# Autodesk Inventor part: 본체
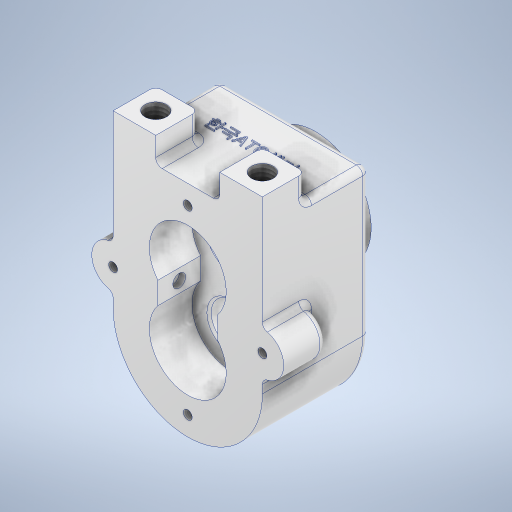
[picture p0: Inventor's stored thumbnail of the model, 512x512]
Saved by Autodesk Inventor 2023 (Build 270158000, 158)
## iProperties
Created: 2024-03
Part Number: 본체
Material: 알루미늄 6061
Document SubType Name: Modeling
Designer: asung
Density: 2.7 g/cm^3
Appearance: 알루미늄 - 평지
Author: asung
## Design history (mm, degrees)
sketch "스케치1"
  geometry: L1 (0, 0)-(0, 68); L2 (-35, 0)-(-35, 68); L3 (35, 0)-(35, 68); L4 (-35, 68)-(35, 68); C1 r 35 at (0, 0); 3 further points
  constraints: 8 end point, 2 parallel, 1 centre point, 1 coincident, 1 horizontal, 1 vertical
  dimensions: "d0" = 70 diameter of C1; "d1" = 68 distance of L1.start L1.end; "d2" = 35 distance between parallel lines of L1 L2; "d3" = 35 distance between parallel lines of L1 L3; "d4" = 68 distance from line of point (0, 0) L4; "d5" = 68 distance from line of L3.start L4; "d6" = 68 distance from line of L2.start L4
extrude "돌출1" new body sketch "스케치1" stored distance "d7" = 50; taper "d8" = 0 deg
sketch "스케치2"
  geometry: L1 (0, 50)-(0, 0) reference; L2 (70, 0)-(0, 0) reference; L3 (70, 0)-(70, 50) reference; L4 (0, 50)-(70, 50) reference; L5 (0, 0)-(20, 0); L6 (20, 0)-(20, 20); L7 (20, 20)-(0, 20); L8 (0, 20)-(0, 0); L9 (70, 0)-(50, 0); L10 (50, 0)-(50, 20); L11 (50, 20)-(70, 20); L12 (70, 20)-(70, 0); 5 further points
  constraints: 16 end point, 4 parallel, 2 horizontal, 2 perpendicular
  dimensions: "d9" = 20 distance of L7.end L6.end; "d10" = 20 distance of L6.end L5.end; "d11" = 20 distance of L10.end L11.end; "d12" = 20 distance of L9.end L10.end
extrude "돌출2" join sketch "스케치2" distance "d13" = 12; taper "d14" = 0 deg
fillet "모깎기1" dims "d15" = 3
fillet "모깎기2" dims "d16" = 3
sketch "스케치3"
  geometry: L1 (12, 68)-(-12, 68) reference; L2 (-15, 71)-(-15, 80) reference; L3 (-35, 80)-(-15, 80) reference; L4 (-35, 0)-(-35, 80) reference; L5 (35, 0)-(35, 80) reference; L6 (15, 80)-(35, 80) reference; L7 (15, 71)-(15, 80) reference; L8 (0, 68)-(0, 40); C1 r 10 at (-35, 16.5); C2 r 10 at (35, 16.5); A1 r 3 centre (-12, 71) between (-15, 71) and (-12, 68) reference; A2 r 35 centre (0, 0) between (-35, 0) and (35, 0) reference; A3 r 3 centre (12, 71) between (12, 68) and (15, 71) reference; 5 further points
  constraints: 2 centre point, 2 end point, 1 midpoint, 1 point on line, 1 symmetric about line, 1 vertical, 1 other
  dimensions: "d17" = 10 radius of C1; "d18" = 63.5 distance from line of C1.centre L3
extrude "돌출3" join sketch "스케치3" distance "d19" = 20; taper "d20" = 0 deg
fillet "모깎기3" dims "d21" = 3
fillet "모깎기4" dims "d22" = 3
sketch "스케치4"
  geometry: L1 (12, 68)-(-12, 68) reference; L2 (-15, 71)-(-15, 80) reference; L3 (-35, 80)-(-15, 80) reference; L4 (-35, 29.149)-(-35, 80) reference; L5 (-35, 0)-(-35, 3.851) reference; L6 (35, 0)-(35, 3.851) reference; L7 (35, 29.149)-(35, 80) reference; L8 (15, 80)-(35, 80) reference; L9 (15, 71)-(15, 80) reference; L10 (0, 33)-(0, 0); L11 (-14, 21.686)-(-14, 11.314); L12 (14, 21.686)-(14, 11.314); A1 r 3 centre (-12, 71) between (-15, 71) and (-12, 68) reference; A2 r 3 centre (-38, 29.149) between (-37.308, 26.23) and (-35, 29.149) reference; A3 r 10 centre (-35, 16.5) between (-37.308, 26.23) and (-37.308, 6.77) reference; A4 r 3 centre (-38, 3.851) between (-35, 3.851) and (-37.308, 6.77) reference; A5 r 35 centre (0, 0) between (-35, 0) and (35, 0) reference; A6 r 3 centre (38, 3.851) between (37.308, 6.77) and (35, 3.851) reference; A7 r 10 centre (35, 16.5) between (37.308, 6.77) and (37.308, 26.23) reference; A8 r 3 centre (38, 29.149) between (35, 29.149) and (37.308, 26.23) reference; A9 r 3 centre (12, 71) between (12, 68) and (15, 71) reference; A10 r 18 centre (0, 33) between (14, 21.686) and (-14, 21.686); A11 r 18 centre (0, 0) between (-14, 11.314) and (14, 11.314); 2 further points
  constraints: 6 end point, 4 point on circle, 2 centre point, 2 parallel, 1 midpoint, 1 vertical, 1 vertical alignment
  dimensions: "d23" = 36 diameter of A10; "d24" = 35 distance from line of L10.start L1; "d25" = 36 diameter of A11; "d26" = 33 distance of L10.end L10.start; "d27" = 14 distance between parallel lines of L10 L11; "d28" = 14 distance between parallel lines of L10 L12
extrude "돌출4" cut sketch "스케치4" distance "d29" = 20; taper "d30" = 0 deg
sketch "스케치5"
  geometry: L1 (35, 68)-(-35, 68) reference; L2 (-35, 68)-(-35, 0) reference; L3 (35, 0)-(35, 68) reference; C1 r 26 at (0, 33); A1 r 35 centre (0, 0) between (-35, 0) and (35, 0) reference; 2 further points
  constraints: 1 centre point, 1 midpoint, 1 vertical alignment
  dimensions: "d31" = 52 diameter of C1; "d32" = 35 distance from line of L1 C1.centre
extrude "돌출5" join sketch "스케치5" distance "d33" = 10; taper "d34" = 0 deg
sketch "스케치6"
  geometry: C1 r 26 at (0, 0) reference; C2 r 16 at (0, 0); A1 r 18 centre (0, 0) between (14, -11.314) and (-14, -11.314) reference; 1 further point
  constraints: 1 centre point, 1 coincident
  dimensions: "d35" = 32 diameter of C2
extrude "돌출6" join sketch "스케치6" distance "d36" = 4; taper "d37" = 0 deg
chamfer "모따기1" distance "d38" = 1; stored, may be unused: second distance "d39" = 2, angle "d40" = 45 deg
fillet "모깎기5" dims "d41" = 3
sketch "스케치7"
  geometry: A1 r 18 centre (0, 33) between (14, 21.686) and (-14, 21.686) reference; 2 further points
  constraints: 1 coincident
hole "구멍1" sketch "스케치7" at (0, 33) diameter "d42" = 15; stored, may be unused: countersink angle "d46" = 90 deg, drill point angle "d48" = 0 deg; dims "d43" = 8, "d44" = 20, "d45" = 10, "d47" = 30
sketch "스케치8"
  geometry: C1 r 15 at (0, 0) reference; 2 further points
  constraints: 1 coincident
hole "구멍2" sketch "스케치8" at (0, 0) diameter "d49" = 15; stored, may be unused: countersink angle "d53" = 90 deg, drill point angle "d55" = 0 deg; dims "d50" = 6, "d51" = 25, "d52" = 7.3, "d54" = 30
sketch "스케치9"
  geometry: A1 r 18 centre (0, 0) between (-14, 11.314) and (14, 11.314) reference; 2 further points
  constraints: 1 coincident
hole "구멍3" sketch "스케치9" at (0, 0) diameter "d59" = 20; stored, may be unused: countersink angle "d63" = 90 deg, drill point angle "d65" = 0 deg; dims "d60" = 6, "d61" = 25, "d62" = 7.3, "d64" = 10
chamfer "모따기3" distance "d66" = 1; stored, may be unused: second distance "d67" = 2, angle "d68" = 45 deg
sketch "스케치10"
  geometry: L1 (7, -35)-(7, -28) reference; L2 (17, -35)-(7, -35) reference; L3 (17, -38)-(17, -35) reference; L4 (18, -39)-(17, -38) reference; L5 (25.5, -31.7)-(20.5, -31.7) reference; L6 (25.5, -5)-(25.5, -31.7) reference; L7 (23, -5)-(25.5, -5) reference; L8 (43, 5)-(51, 5) reference; L9 (51, 5)-(51, 25) reference; L10 (51, 25)-(68, 25) reference; L11 (68, 25)-(68, -25) reference; L12 (68, -25)-(62, -25) reference; L13 (4, -25)-(-35, -25) reference; L14 (-35, -25)-(-35, 25) reference; L15 (-35, 25)-(-18, 25) reference; L16 (-18, 25)-(-18, 5) reference; L17 (-18, 5)-(-11, 5) reference; L18 (-11, 5)-(-10, 4) reference; L19 (-10, 4)-(-10, -5) reference; L20 (-10, -5)-(10, -5) reference; L21 (10, -5)-(10, 4) reference; L22 (10, 4)-(11, 5) reference; L23 (11, 5)-(23, 5) reference; L24 (40.5, -5)-(43, -5) reference; L25 (40.5, -31.7)-(40.5, -5) reference; L26 (45.5, -31.7)-(40.5, -31.7) reference; L27 (49, -38)-(48, -39) reference; L28 (49, -35)-(49, -38) reference; L29 (59, -35)-(49, -35) reference; L30 (59, -28)-(59, -35) reference; L31 (0, -25)-(0, 25) reference; L32 (10, -5)-(-10, -5) reference; L33 (7, -5)-(0, -9.041); L34 (23, 5)-(23, -5) reference; L35 (20.5, -31.7)-(20.5, -39) reference; L36 (20.5, -39)-(18, -39) reference; L37 (48, -39)-(45.5, -39) reference; L38 (45.5, -39)-(45.5, -31.7) reference; L39 (43, -5)-(43, 5) reference; A1 r 3 centre (4, -28) between (4, -25) and (7, -28) reference; A2 r 3 centre (62, -28) between (59, -28) and (62, -25) reference; 3 further points
  constraints: 2 end point, 2 point on line
  dimensions: "d70" = 7 distance from line of L31 L33.start; "d71" = 60 deg angle of L31 L33
revolve "회전1" sketch "스케치10" stored, may be unused: angle "d72" = 90 deg
sketch "스케치11"
  geometry: L1 (0, 0)-(0, -26); L2 (-14, 11.314)-(-14, 21.686) reference; L3 (14, 21.686)-(14, 11.314) reference; L4 (12, 68)-(-12, 68) reference; L5 (-15, 71)-(-15, 80) reference; L6 (-35, 80)-(-15, 80) reference; L7 (-35, 29.149)-(-35, 80) reference; L8 (-35, 0)-(-35, 3.851) reference; L9 (35, 0)-(35, 3.851) reference; L10 (35, 29.149)-(35, 80) reference; L11 (15, 80)-(35, 80) reference; L12 (15, 71)-(15, 80) reference; L13 (0, 33)-(0, 59); C1 r 29 at (0, 33) reference; A1 r 18 centre (0, 0) between (-14, 11.314) and (14, 11.314) reference; A2 r 18 centre (0, 33) between (14, 21.686) and (-14, 21.686) reference; A3 r 3 centre (-12, 71) between (-15, 71) and (-12, 68) reference; A4 r 3 centre (-38, 29.149) between (-37.308, 26.23) and (-35, 29.149) reference; A5 r 10 centre (-35, 16.5) between (-37.308, 26.23) and (-37.308, 6.77) reference; A6 r 3 centre (-38, 3.851) between (-35, 3.851) and (-37.308, 6.77) reference; A7 r 35 centre (0, 0) between (-35, 0) and (35, 0) reference; A8 r 3 centre (38, 3.851) between (37.308, 6.77) and (35, 3.851) reference; A9 r 10 centre (35, 16.5) between (37.308, 6.77) and (37.308, 26.23) reference; A10 r 3 centre (38, 29.149) between (35, 29.149) and (37.308, 26.23) reference; A11 r 3 centre (12, 71) between (12, 68) and (15, 71) reference; 4 further points
  constraints: 4 coincident, 4 end point, 2 vertical
  dimensions: "d73" = 26 distance of L1.start L1.end; "d74" = 26 distance of L13.start L13.end
hole "구멍4" sketch "스케치11" at (0, -26), (35, 16.5), (-35, 16.5), (0, 59) diameter "d75" = 4.134; stored, may be unused: countersink angle "d79" = 90 deg, drill point angle "d81" = 118 deg; dims "d76" = 10, "d77" = 4, "d78" = 2, "d80" = 12
sketch "스케치12" dims "d82" = 42
  geometry: C1 r 26 at (0, 0) reference; C2 r 7.5 at (0, 0) reference; 3 further points
  constraints: 1 coincident, 1 vertical alignment, 2 other
hole "구멍5" sketch "스케치12" at (0, 21) diameter "d83" = 3.242; stored, may be unused: countersink angle "d87" = 90 deg, drill point angle "d89" = 118 deg; dims "d84" = 8, "d85" = 4, "d86" = 2, "d88" = 10
sketch "스케치13"
  geometry: L1 (18, -39)-(17, -38) reference; L2 (17, -38)-(17, -35) reference; L3 (17, -35)-(13.621, -35) reference; L4 (13.621, -35)-(13.621, -25) reference; L5 (13.621, -25)-(12, -24.026) reference; L6 (12, -24.026)-(10.379, -25) reference; L7 (10.379, -25)-(10.379, -35) reference; L8 (10.379, -35)-(7, -35) reference; L9 (7, -35)-(7, -28) reference; L10 (4, -25)-(-35, -25) reference; L11 (-35, -25)-(-35, 25) reference; L12 (-35, 25)-(-28.067, 25) reference; L13 (-28.067, 25)-(-28.067, 13) reference; L14 (-28.067, 13)-(-26, 11.758) reference; L15 (-26, 11.758)-(-23.933, 13) reference; L16 (-23.933, 13)-(-23.933, 25) reference; L17 (-23.933, 25)-(-18, 25) reference; L18 (-18, 25)-(-18, 5) reference; L19 (-18, 5)-(-11, 5) reference; L20 (-11, 5)-(-10, 4) reference; L21 (-10, 4)-(-10, -5) reference; L22 (-10, -5)-(-7, -5) reference; L23 (-7, -5)-(0, -9.041) reference; L24 (0, -9.041)-(7, -5) reference; L25 (7, -5)-(10, -5) reference; L26 (10, -5)-(10, 4) reference; L27 (10, 4)-(11, 5) reference; L28 (11, 5)-(23, 5) reference; L29 (23, 5)-(23, -5) reference; L30 (23, -5)-(25.5, -5) reference; L31 (25.5, -5)-(25.5, -31.7) reference; L32 (25.5, -31.7)-(20.5, -31.7) reference; L33 (20.5, -31.7)-(20.5, -39) reference; L34 (20.5, -39)-(18, -39) reference; L35 (49, -38)-(48, -39) reference; L36 (48, -39)-(45.5, -39) reference; L37 (45.5, -39)-(45.5, -31.7) reference; L38 (45.5, -31.7)-(40.5, -31.7) reference; L39 (40.5, -31.7)-(40.5, -5) reference; L40 (40.5, -5)-(43, -5) reference; L41 (43, -5)-(43, 5) reference; L42 (43, 5)-(51, 5) reference; L43 (51, 5)-(51, 25) reference; L44 (51, 25)-(56.933, 25) reference; L45 (56.933, 25)-(56.933, 13) reference; L46 (56.933, 13)-(59, 11.758) reference; L47 (59, 11.758)-(61.067, 13) reference; L48 (61.067, 13)-(61.067, 25) reference; L49 (61.067, 25)-(68, 25) reference; L50 (68, 25)-(68, -25) reference; L51 (68, -25)-(62, -25) reference; L52 (59, -28)-(59, -35) reference; L53 (59, -35)-(55.621, -35) reference; L54 (55.621, -35)-(55.621, -25) reference; L55 (55.621, -25)-(54, -24.026) reference; L56 (54, -24.026)-(52.379, -25) reference; L57 (52.379, -25)-(52.379, -35) reference; L58 (52.379, -35)-(49, -35) reference; L59 (49, -35)-(49, -38) reference; L60 (45.5, -31.7)-(45.5, -39) reference; L61 (45.5, -38.3)-(45.904, -39); L62 (48, -39)-(18, -39) reference; L63 (33, -39)-(33, -30); A1 r 3 centre (4, -28) between (7, -28) and (4, -25) reference; A2 r 3 centre (62, -28) between (62, -25) and (59, -28) reference; 4 further points
  constraints: 4 end point, 2 midpoint, 2 point on line, 1 vertical
  dimensions: "d93" = 0.7 vertical distance of L61.start point (46.75, -39); "d94" = 30 deg angle of L37 L61
revolve "회전2" sketch "스케치13" stored, may be unused: angle "d95" = 90 deg
sketch "스케치15"
  geometry: L1 (17, 20)-(0, 20) reference; L2 (0, 20)-(0, 0) reference; L3 (0, 0)-(20, 0) reference; L4 (20, 0)-(20, 17) reference; L5 (50, 17)-(50, 0) reference; L6 (50, 0)-(70, 0) reference; L7 (70, 0)-(70, 20) reference; L8 (70, 20)-(53, 20) reference; A1 r 3 centre (17, 17) between (20, 17) and (17, 20) reference; A2 r 3 centre (53, 17) between (53, 20) and (50, 17) reference; 3 further points
  dimensions: "d103" = 10 distance from line of L1 point (10, 10); "d104" = 10 distance from line of L4 point (10, 10); "d105" = 10 distance from line of L8 point (60, 10); "d106" = 10 distance from line of L7 point (60, 10)
hole "구멍6" sketch "스케치15" at (10, 10), (60, 10) diameter "d107" = 10.106; stored, may be unused: countersink angle "d111" = 90 deg, drill point angle "d113" = 0 deg; dims "d108" = 14, "d109" = 4, "d110" = 2, "d112" = 16
node "작업 평면1"
sketch "스케치16"
  geometry: L1 (14, 11.314)-(14, 21.686) reference; L2 (-14, 21.686)-(-14, 11.314) reference; L3 (-12, 68)-(12, 68) reference; L4 (15, 71)-(15, 80) reference; L5 (15, 80)-(19.947, 80) reference; L6 (19.947, 80)-(19.947, 64) reference; L7 (19.947, 64)-(30.053, 64) reference; L8 (30.053, 64)-(30.053, 80) reference; L9 (30.053, 80)-(35, 80) reference; L10 (35, 80)-(35, 29.149) reference; L11 (35, 3.851)-(35, 0) reference; L12 (-35, 0)-(-35, 3.851) reference; L13 (-35, 29.149)-(-35, 80) reference; L14 (-35, 80)-(-30.053, 80) reference; L15 (-30.053, 80)-(-30.053, 64) reference; L16 (-30.053, 64)-(-19.947, 64) reference; L17 (-19.947, 64)-(-19.947, 80) reference; L18 (-19.947, 80)-(-15, 80) reference; L19 (-15, 80)-(-15, 71) reference; L20 (-19.947, 64)-(-30.053, 64) reference; L21 (-25, 64)-(-25, 24.5); L22 (-14, 11.314)-(-14, 21.686) reference; L23 (-14, 16.5)-(-17, 16.5); L24 (-35, 68)-(35, 68) reference; L25 (0, 68)-(0, 48.896); L26 (25, 64)-(25, 24.5); L27 (14, 16.5)-(17, 16.5); L28 (-28, 64)-(-28, 24.5); L29 (-17, 13.5)-(-14, 13.5); L30 (-25, 24.5)-(-28, 24.5); L31 (-17, 16.5)-(-17, 13.5); L32 (-14, 13.5)-(-14, 16.5); C1 r 2.067 at (-35, 16.5) reference; C2 r 2.067 at (0, -26) reference; C3 r 2.067 at (35, 16.5) reference; C4 r 2.067 at (0, 59) reference; A1 r 18 centre (0, 0) between (-14, 11.314) and (14, 11.314) reference; A2 r 18 centre (0, 33) between (14, 21.686) and (-14, 21.686) reference; A3 r 3 centre (-12, 71) between (-15, 71) and (-12, 68) reference; A4 r 3 centre (12, 71) between (12, 68) and (15, 71) reference; A5 r 3 centre (38, 29.149) between (35, 29.149) and (37.308, 26.23) reference; A6 r 10 centre (35, 16.5) between (37.308, 6.77) and (37.308, 26.23) reference; A7 r 3 centre (38, 3.851) between (37.308, 6.77) and (35, 3.851) reference; A8 r 35 centre (0, 0) between (-35, 0) and (35, 0) reference; A9 r 3 centre (-38, 3.851) between (-35, 3.851) and (-37.308, 6.77) reference; A10 r 10 centre (-35, 16.5) between (-37.308, 26.23) and (-37.308, 6.77) reference; A11 r 3 centre (-38, 29.149) between (-37.308, 26.23) and (-35, 29.149) reference; A12 r 8 centre (-17, 24.5) between (-25, 24.5) and (-17, 16.5); A13 r 8 centre (17, 24.5) between (17, 16.5) and (25, 24.5); A14 r 11 centre (-17, 24.5) between (-28, 24.5) and (-17, 13.5); 6 further points
  constraints: 20 end point, 6 point on circle, 5 symmetric about line, 3 centre point, 3 midpoint, 3 vertical, 2 perpendicular, 2 tangent, 1 collinear, 1 horizontal, 1 point on line, 3 other
  dimensions: "d114" = 63.5 distance of L21.start point (-25, 0.5); "d115" = 8 radius of A12; "d116" = 3 distance between parallel lines of L21 L28
  node "절단 모서리 투영4"
revolve "회전3" stored, may be unused: angle "d117" = 90 deg
revolve "회전4" stored, may be unused: angle "d118" = 90 deg
fillet "모깎기6" dims "d119" = 3
sketch "스케치17"
  geometry: L1 (-20, 23)-(-20, 47) reference; L2 (-6, 23)-(-20, 23) reference; L3 (0, 0)-(0, 17) reference; L4 (24, 0)-(0, 0) reference; L5 (24, 17)-(24, 0) reference; L6 (44, 23)-(30, 23) reference; L7 (44, 47)-(44, 23) reference; L8 (-20, 47)-(44, 47) reference; A1 r 6 centre (-6, 17) between (0, 17) and (-6, 23) reference; A2 r 6 centre (30, 17) between (30, 23) and (24, 17) reference; 2 further points
  constraints: 1 vertical alignment, 1 other
  dimensions: "d120" = 30 distance from line of point (12, 30) L4
feature "엠보싱1" sketch "스케치17" dims "d121" = 0.5, "d122" = 0
chamfer "모따기4" distance "d123" = 1; stored, may be unused: second distance "d124" = 2, angle "d125" = 45 deg
chamfer "모따기5" distance "d126" = 1; stored, may be unused: second distance "d127" = 2, angle "d128" = 45 deg
node "솔리드1"
pattern_circular "원형 패턴1" dims angle "d91" = 360 deg
mirror "미러1"
node "투영된 루프1"
node "투영된 루프2"
node "투영된 루프3"
node "투영된 루프4"
node "투영된 루프5"
node "투영된 루프8"
node "투영된 루프9"
node "투영된 루프10"
node "절단 모서리 투영1"
node "절단 모서리 투영2"
feature "A9D066F2-1C7D-4E18-AEED-F7BC21143FA4" dims "d42" = 15, "d43" = 8, "d44" = 20, "d45" = 10, "d46" = 90 deg, "d47" = 30, "d48" = 0
